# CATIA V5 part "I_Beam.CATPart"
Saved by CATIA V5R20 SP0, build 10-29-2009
Part number: Part2
Material "Iron": density 7870 kg/m3, Young's modulus 1.2e+11 Pa, Poisson ratio 0.291, thermal expansion 1.21e-05 1/K
Bounding box of the stored display mesh (mm): x -30 to 30, y 0 to 200, z -30 to 30
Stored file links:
  M:\카티아자료\수업자료\툴바예제\7 PEO and GSA\I_Beam.CATPart
  C:\Program Files (x86)\Dassault Systemes\B18\intel_a\startup\materials\Catalog.CATMaterial
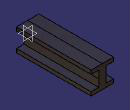
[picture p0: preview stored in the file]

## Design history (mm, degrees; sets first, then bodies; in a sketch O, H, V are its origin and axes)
Parameters
  VOLUME = 0.0004 (volume) {= smartVolume(Body1 )}
Body1 (main body), material "Iron"
  Sketch1 on zx-plane, origin (0, 0, 0), H (-1, 0, 0), V (0, 0, 1)
    line L1 (10, 0) -> (10, 20)
    point P1 (10, 0)
    point P2 (10, 20)
    line L2 (-10, 0) -> (-10, 20)
    point P3 (-10, 0)
    point P4 (-10, 20)
    line L3 (-10, 20) -> (-30, 20)
    point P5 (-30, 20)
    line L4 (-30, 20) -> (-30, 30)
    point P6 (-30, 30)
    line L5 (-30, 30) -> (0, 30)
    point P7 (0, 30)
    point P8 (30, 20)
    point P9 (10, 20)
    line L6 (10, 20) -> (30, 20)
    point P10 (30, 30)
    line L7 (30, 20) -> (30, 30)
    point P11 (0, 30)
    line L8 (30, 30) -> (0, 30)
    point P12 (10, 0)
    point P13 (10, -20)
    point P14 (-10, 0)
    point P15 (-10, -20)
    point P16 (-30, -20)
    point P17 (-30, -30)
    point P18 (0, -30)
    point P19 (30, -20)
    point P20 (10, -20)
    point P21 (30, -30)
    point P22 (0, -30)
    line L9 (10, 0) -> (10, -20)
    line L10 (-10, 0) -> (-10, -20)
    line L11 (-10, -20) -> (-30, -20)
    line L12 (-30, -20) -> (-30, -30)
    line L13 (-30, -30) -> (0, -30)
    line L14 (10, -20) -> (30, -20)
    line L15 (30, -20) -> (30, -30)
    line L16 (30, -30) -> (0, -30)
    distance L6 H = 20
    distance L7 L4 = 60
    distance L16 L14 = 10
    distance L2 L1 = 20
    coincidence: P1 H, P3 H, P7 V, P2 P9
    vertical: L1 V, L2 V, L4 V
    horizontal: L3 H, L5 H
    symmetry: P5 P8 V, P4 P9 V, L3 L6 V, P6 P10 V, L4 L7 V, P7 P11 V, L5 L8 V, L1 L2 V, P1 P12 H, P2 P13 H, P3 P14 H, P4 P15 H, P5 P16 H, P6 P17 H, P7 P18 H, P8 P19 H, P9 P20 H, P10 P21 H, P11 P22 H, L1 L9 H, L2 L10 H, L3 L11 H, L4 L12 H, L5 L13 H, L6 L14 H, L7 L15 H, L8 L16 H
  Pad1: profile Sketch1, direction (0, 1, 0), length 200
